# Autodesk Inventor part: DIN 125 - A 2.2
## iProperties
Comments: To add or edit properties for Autodesk Inventor files, use iProperties.
Created: 2004-07
Part Number: DIN 125 - A 2.2
Vendor: Autodesk Inc.
Document SubType Name: Modeling
Designer: John Blackburn
Material: Default
Description: Washer
Standard: DIN 125
Alert: To add or edit properties for Autodesk Inventor files, use iProperties.
Control State: 0
Master: False
Checked Out: False
Shininess: 64.0
Length Units: 11269
Angle Units: 11279
Time Units: 11290
Mass Units: 11283
Length Display Precision: 3
Angle Display Precision: 2
Compacted: True
Classification: un/spsc 31161807
Density: 0.0
Volumn: 0.0
Area: 0.0
PropertySet Name: Model Information
Author: John Blackburn
Revision Number: 8
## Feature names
1. Body [Extrusion]
